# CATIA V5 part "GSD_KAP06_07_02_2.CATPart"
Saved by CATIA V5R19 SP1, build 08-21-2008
Part number: GSD_SWEEP_LINE_01
Definition: Beispielmodell für die Funktion Translation - Linie / Sweep - Line.
Description: CATIA V5 Flächenmodellierung  Copyright (c) 2009 Maik Hertha IT Consultants
Bounding box of the stored display mesh (mm): x -121.443 to 116.438, y -32.861 to -13.354, z -39.945 to 0
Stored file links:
  \GSD_BUCH_UEBUNG\GSD_KAP06_07_02_2.CATPart
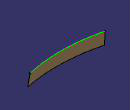
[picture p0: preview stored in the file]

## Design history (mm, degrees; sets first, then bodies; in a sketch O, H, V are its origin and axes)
AxisSystem1: origin (0, 0, 0), X (1, 0, 0), Y (0, 1, 0), Z (0, 0, 1)
Set1
  Sketch1 on xy-plane, origin (0, 0, 0), H (1, 0, 0), V (0, 1, 0)
    line L1 (112.3223, -3.1639) -> (39.7788, -15.7993)
    arc A1 centre (0, -20) radius 40 from (39.7788, -15.7993) to (-39.6088, -14.4195) cw
    point P3 (0, -20)
    line L2 (-39.6088, -14.4195) -> (-120.363, -4.0213)
    construction line L3 (13.9125, -20) -> (-11.1781, -20)
    construction line L4 (39.2477, 0) -> (-28.2488, 0)
    point P8 (39.2477, 0)
    construction line L5 (0, 7.9755) -> (0, -63.4676)
    point P10 (0, 7.9755)
    curve C1
    spline S1 through (-120.9377, -13.3542) (-46.9511, -26.3635) (48.4251, -27.4184) (115.1771, -16.8703)
    curve C2
    distance L3 L4 = 20
    radius A1 = 40
    horizontal: L3 H, L4 H
    coincidence: P8 H, P10 V, P3 L5, P3 L3
    vertical: L5 V
Set2
  DatumCurve1: linked copy from another document
  Sweep1: type Segment, Angle 3, Length1 40, Length2 0, DraftDirection (0, 0, 1), DraftAngleLoc (edge of DatumCurve1; edge of DatumCurve1; edge of DatumCurve1), Angle##1## 3, Angle##2## 5, Angle##3## 8, GuideCrv DatumCurve1
Set3
  DatumCurve2: linked copy from another document
  Sweep2: type Segment, Angle 3, Length1 40, Length2 0, DraftDirection (0, 0, 1), DraftAngleLoc ({point type OnCurve, Support DatumCurve2, Ratio 0}; {point type OnCurve, Support DatumCurve2, Ratio 0.5}; {point type OnCurve, Support DatumCurve2, Ratio 1}), Angle 3, Angle 5, Angle 8, GuideCrv DatumCurve2
Body1 (main body)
